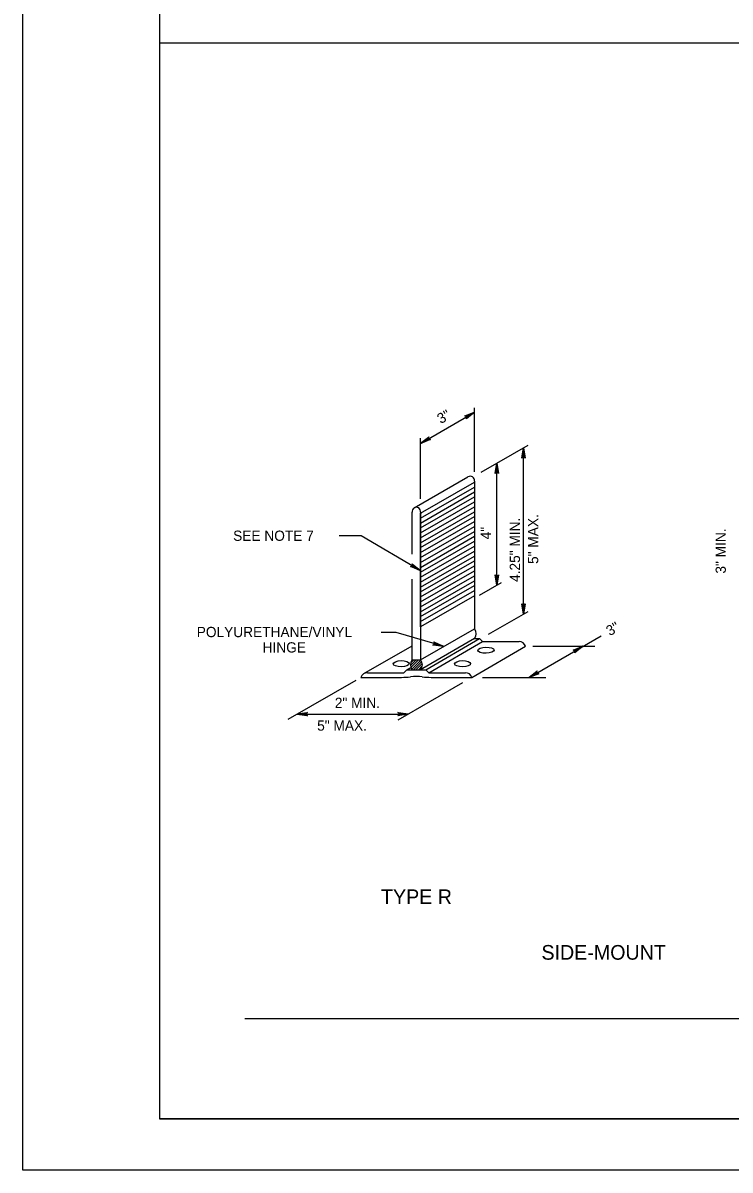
# Model space of a CAD drawing. Extents: x 640253 to 641999, y 298458 to 299646.
# Drawn here: x 640253.3 to 640460.4, y 298457.6 to 298793.5 of the extents above; entities that cross this region are included whole.
import ezdxf

# ---------------------------------------------------------------- set-up
doc = ezdxf.new("R2010")
doc.units = 0
for name, color, linetype in [('1', 7, 'Continuous'), ('2', 7, 'Continuous'), ('PLT-BNDY', 7, 'Continuous')]:
    doc.layers.add(name, color=color, linetype=linetype)

msp = doc.modelspace()

# ---------------------------------------------------------------- linework, layer by layer
at = {"layer": '1'}
for p, q in [((640293.31, 299036.63), (640293.31, 298472.63)), ((640293.31, 298787.67), (641079.31, 298787.67)), ((640318.26, 298501.97), (640782.88, 298501.97)), ((641079.31, 298472.63), (640293.31, 298472.63)), ((640293.31, 298472.63), (640879.31, 298472.63))]:
    msp.add_line(p, q, dxfattribs=at)
at = {"layer": '2'}
for p, q in [((640369.76, 298670.43), (640385.5, 298679.52)), ((640385.5, 298662.1), (640385.5, 298680.83)), ((640369.76, 298654.18), (640369.76, 298671.9)), ((640387.48, 298661.95), (640401.21, 298669.87)), ((640399.85, 298620.44), (640399.85, 298669.09)), ((640392.09, 298628.92), (640392.09, 298664.61)), ((640367.87, 298651.54), (640383.62, 298660.63)), ((640385.5, 298659.34), (640385.5, 298616.13)), ((640369.76, 298648.55), (640385.5, 298657.63)), ((640369.76, 298647.1), (640385.5, 298656.19)), ((640369.76, 298645.66), (640385.5, 298654.75)), ((640369.76, 298644.22), (640385.5, 298653.3)), ((640367.26, 298637.98), (640367.26, 298650.25)), ((640369.76, 298642.77), (640385.5, 298651.86)), ((640369.76, 298641.33), (640385.5, 298650.42)), ((640369.76, 298650.25), (640369.76, 298607.04)), ((640369.76, 298649.71), (640369.99, 298650.11)), ((640369.76, 298649.75), (640369.95, 298650.09)), ((640369.76, 298639.89), (640385.5, 298648.97)), ((640369.76, 298638.44), (640385.5, 298647.53)), ((640369.76, 298637), (640385.5, 298646.09)), ((640352.35, 298643.33), (640345.91, 298643.33)), ((640369.63, 298633.22), (640352.35, 298643.33)), ((640369.76, 298635.56), (640385.5, 298644.64)), ((640369.76, 298634.11), (640385.5, 298643.2)), ((640369.76, 298632.67), (640385.5, 298641.76)), ((640369.76, 298631.22), (640385.5, 298640.31)), ((640369.76, 298629.78), (640385.5, 298638.87)), ((640369.76, 298628.34), (640385.5, 298637.43)), ((640369.76, 298626.9), (640385.5, 298635.98)), ((640369.76, 298625.45), (640385.5, 298634.54)), ((640369.76, 298624.01), (640385.5, 298633.1)), ((640367.26, 298607.04), (640367.26, 298630.65)), ((640369.76, 298622.56), (640385.5, 298631.65)), ((640369.76, 298621.12), (640385.5, 298630.21)), ((640386.97, 298625.96), (640393.4, 298629.67)), ((640369.76, 298619.68), (640385.5, 298628.77)), ((640369.76, 298618.24), (640385.5, 298627.32)), ((640389.66, 298614.56), (640401.21, 298621.22)), ((640369.76, 298607.04), (640385.5, 298616.13)), ((640362.57, 298615.03), (640358.24, 298615.03)), ((640376.36, 298610.99), (640362.57, 298615.03)), ((640385.5, 298613.24), (640369.76, 298604.15)), ((640371.26, 298604.15), (640387, 298613.24)), ((640372.13, 298603.27), (640387.88, 298612.37)), ((640385.5, 298613.24), (640387, 298613.24)), ((640387, 298613.24), (640387.88, 298612.37)), ((640387.88, 298612.37), (640398.6, 298612.37)), ((640401.49, 298601.9), (640422.6, 298614.08)), ((640353.17, 298603.01), (640367.26, 298611.14)), ((640384.75, 298601.9), (640400.5, 298610.99)), ((640402.58, 298610.99), (640420.81, 298610.99)), ((640366.78, 298605.37), (640368.45, 298607.04)), ((640366.85, 298606.14), (640367.74, 298607.04)), ((640366.91, 298604.79), (640369.16, 298607.04)), ((640367.14, 298604.32), (640369.8, 298606.97)), ((640367.26, 298607.04), (640369.76, 298607.04)), ((640367.68, 298604.15), (640370.07, 298606.54)), ((640368.39, 298604.15), (640370.22, 298605.99)), ((640354.16, 298603.27), (640364.88, 298603.27)), ((640365.76, 298604.15), (640364.88, 298603.27)), ((640365.76, 298604.15), (640366.88, 298604.8)), ((640365.76, 298604.15), (640371.26, 298604.15)), ((640369.1, 298604.15), (640370.23, 298605.29)), ((640369.76, 298604.15), (640369.76, 298604.15)), ((640371.26, 298604.15), (640372.13, 298603.27)), ((640372.13, 298603.27), (640382.85, 298603.27)), ((640331.01, 298589.63), (640350.88, 298601.1)), ((640352.26, 298601.9), (640364.16, 298601.9)), ((640363.15, 298589.43), (640382.07, 298600.35)), ((640372.86, 298601.9), (640384.75, 298601.9)), ((640387.83, 298601.9), (640406.4, 298601.9)), ((640333.6, 298591.13), (640366.09, 298591.13))]:
    msp.add_line(p, q, dxfattribs=at)
for points in [[(640382.85, 298678.41), (640383.04, 298678.28), (640385.5, 298679.52), (640382.85, 298678.41), (640382.66, 298678.44), (640385.5, 298679.52), (640383.19, 298678.03), (640383.2, 298677.81), (640385.5, 298679.52), (640383.14, 298677.61), (640383.2, 298677.81)], [(640372.41, 298671.55), (640372.21, 298671.68), (640369.76, 298670.43), (640372.41, 298671.55), (640372.6, 298671.52), (640369.76, 298670.43), (640372.07, 298671.92), (640372.05, 298672.15), (640369.76, 298670.43), (640372.12, 298672.35), (640372.05, 298672.15)], [(640399.5, 298666.24), (640399.7, 298666.34), (640399.85, 298669.09), (640399.5, 298666.24), (640399.37, 298666.09), (640399.85, 298669.09), (640399.99, 298666.35), (640400.19, 298666.25), (640399.85, 298669.09), (640400.33, 298666.09), (640400.19, 298666.25)], [(640391.74, 298661.76), (640391.94, 298661.86), (640392.09, 298664.61), (640391.74, 298661.76), (640391.61, 298661.61), (640392.09, 298664.61), (640392.23, 298661.86), (640392.43, 298661.76), (640392.09, 298664.61), (640392.57, 298661.61), (640392.43, 298661.76)], [(640367.36, 298634.99), (640367.34, 298634.76), (640369.63, 298633.22), (640367.36, 298634.99), (640367.3, 298635.17), (640369.63, 298633.22), (640367.2, 298634.51), (640367.01, 298634.38), (640369.63, 298633.22), (640366.8, 298634.35), (640367.01, 298634.38)], [(640392.45, 298631.77), (640392.25, 298631.66), (640392.09, 298628.92), (640392.45, 298631.77), (640392.58, 298631.92), (640392.09, 298628.92), (640391.96, 298631.66), (640391.75, 298631.76), (640392.09, 298628.92), (640391.62, 298631.92), (640391.75, 298631.76)], [(640400.21, 298623.29), (640400.01, 298623.19), (640399.85, 298620.44), (640400.21, 298623.29), (640400.34, 298623.44), (640399.85, 298620.44), (640399.72, 298623.19), (640399.51, 298623.29), (640399.85, 298620.44), (640399.38, 298623.44), (640399.51, 298623.29)], [(640373.72, 298612.13), (640373.77, 298611.9), (640376.36, 298610.99), (640373.72, 298612.13), (640373.62, 298612.29), (640376.36, 298610.99), (640373.69, 298611.62), (640373.54, 298611.45), (640376.36, 298610.99), (640373.35, 298611.37), (640373.54, 298611.45)], [(640414.6, 298609.88), (640414.79, 298609.75), (640417.25, 298610.99), (640414.6, 298609.88), (640414.41, 298609.91), (640417.25, 298610.99), (640414.94, 298609.5), (640414.95, 298609.28), (640417.25, 298610.99), (640414.89, 298609.08), (640414.95, 298609.28)], [(640404.14, 298603.02), (640403.95, 298603.14), (640401.49, 298601.9), (640404.14, 298603.02), (640404.33, 298602.98), (640401.49, 298601.9), (640403.8, 298603.39), (640403.79, 298603.62), (640401.49, 298601.9), (640403.85, 298603.81), (640403.79, 298603.62)], [(640336.46, 298590.77), (640336.35, 298590.98), (640333.6, 298591.13), (640336.46, 298590.77), (640336.6, 298590.65), (640333.6, 298591.13), (640336.35, 298591.26), (640336.45, 298591.47), (640333.6, 298591.13), (640336.6, 298591.61), (640336.45, 298591.47)], [(640363.24, 298591.49), (640363.34, 298591.28), (640366.09, 298591.13), (640363.24, 298591.49), (640363.09, 298591.61), (640366.09, 298591.13), (640363.35, 298590.99), (640363.25, 298590.79), (640366.09, 298591.13), (640363.09, 298590.65), (640363.25, 298590.79)]]:
    msp.add_lwpolyline(points, dxfattribs=at)
msp.add_lwpolyline([(640369.76, 298616.71), (640369.76, 298649.98), (640385.5, 298659.07), (640385.5, 298625.8)], close=True, dxfattribs=at)
for centre, radius, start, end in [((640384.25, 298659.54), 1.26, 350.9133, 119.9792), ((640368.51, 298650.45), 1.26, 350.9133, 189.0867), ((640383.72, 298614.69), 2.29, 320.9923, 39.0623), ((640398.6, 298610.37), 2, 18.187, 90), ((640369.04, 298605.59), 2.29, 140.9377, 219.0623), ((640367.98, 298605.59), 2.29, 320.9923, 39.0623), ((640354.16, 298601.27), 2, 90, 161.79), ((640368.51, 298589.7), 12.5, 81.9962, 98.0038), ((640382.85, 298601.27), 2, 18.21, 90), ((640364.16, 298620.65), 18.75, 270, 278.0038), ((640372.86, 298620.65), 18.75, 261.9962, 270)]:
    msp.add_arc(centre, radius, start, end, dxfattribs=at)
for centre in [(640388.88, 298609.85), (640364.07, 298605.9), (640382.04, 298605.9)]:
    msp.add_ellipse(centre, major_axis=(2.36, 0.05), ratio=0.379302, dxfattribs=at)
at = {"layer": 'PLT-BNDY'}
msp.add_lwpolyline([(640253.31, 299051.63), (641094.31, 299051.63), (641094.31, 298457.63), (640253.31, 298457.63)], close=True, dxfattribs=at)

# ---------------------------------------------------------------- texts
at = {"layer": '2'}
for s, rotation, p in [('3"', 30, (640375.67, 298676.04)), ('5" MAX.', 90, (640404.2, 298635.11)), ('4.25" MIN.', 90, (640398.86, 298629.84)), ('4"', 90, (640390.34, 298642.31)), ('3" MIN.', 89.9989, (640459.12, 298632.28)), ('3"', 30, (640425.15, 298613.92))]:
    msp.add_text(s, height=3, rotation=rotation, dxfattribs=at).set_placement(p)
for s, height, p in [('SEE NOTE 7', 3, (640314.85, 298641.88)), ('POLYURETHANE/VINYL', 3, (640304.2, 298613.68)), ('HINGE', 3, (640323.48, 298609.18)), ('2" MIN.', 3, (640344.63, 298592.94)), ('5" MAX.', 3, (640339.46, 298586.29)), ('TYPE R', 4.3, (640358.16, 298535.5)), ('SIDE-MOUNT', 4.3, (640405.14, 298519.22))]:
    msp.add_text(s, height=height, dxfattribs=at).set_placement(p)

doc.saveas('drawing.dxf')
